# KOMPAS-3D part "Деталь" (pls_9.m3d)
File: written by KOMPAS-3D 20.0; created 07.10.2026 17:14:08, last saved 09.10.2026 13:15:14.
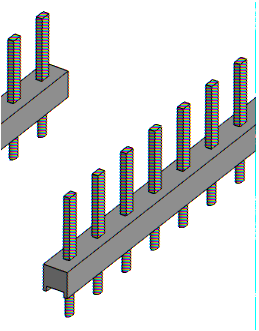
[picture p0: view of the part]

Document properties: Полное имя файла: D:\myProjects\Progect_esp32\box_compas\pls_9.m3d

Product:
- Part/product: Деталь
    Масса: 0.00117316

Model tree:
1. Эскиз:1
2. Элемент выдавливания:1
     Расстояние 1 = 2.5
3. Эскиз:2  (with: Элемент выдавливания:1)
4. Элемент выдавливания:2
     Расстояние 1 = 6
5. Массив по сетке:1  (with: Элемент выдавливания:2, Эскиз:2)  (9 pattern instances)
     Шаг 1 = 2.54; Угол раствора = 90
6. Эскиз:3  (with: Элемент выдавливания:1)
7. Элемент выдавливания:3
     Расстояние 1 = 3
8. Массив по сетке:2  (with: Элемент выдавливания:3, Эскиз:3)  (9 pattern instances)
     Шаг 1 = 2.54; Угол раствора = 90; Геометрический массив = 128
9. Эскиз:4  (with: Элемент выдавливания:1)
10. Элемент выдавливания:4
     Расстояние 2 = 22.86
